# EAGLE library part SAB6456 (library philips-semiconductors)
Sensitive 1 GHz divide-by-64/divide-by-256 switchable prescaler Source: PHILIPS .. SAB6456.pdf
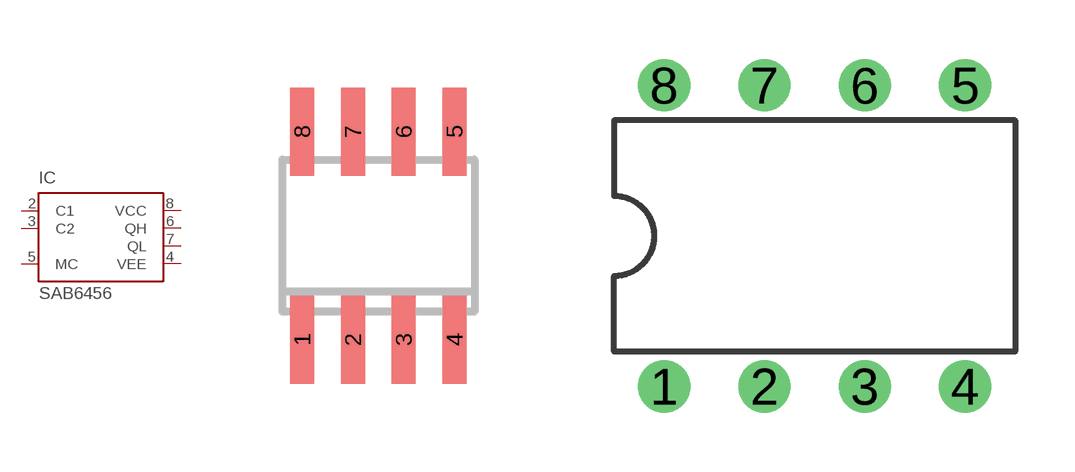
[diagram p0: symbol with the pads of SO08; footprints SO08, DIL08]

Designator prefix IC

## SAB6456T (OC_FARNELL: unknown; OC_NEWARK: unknown)  [SO08]
2  C1  in
3  C2  in
4  VEE  pwr
5  MC  in
6  QH  out
7  QL  out
8  VCC  pwr

## SAB6456 (OC_FARNELL: unknown; OC_NEWARK: unknown)  [DIL08]
Pads as for SO08

## Footprint SO08 (pad centres in mm)
Small Outline Package 8 NS Package M08A
smd 0.6 x 2.2: 1 -1.905,-2.6; 2 -0.635,-2.6; 3 0.635,-2.6; 4 1.905,-2.6; 5 1.905,2.6; 6 0.635,2.6; 7 -0.635,2.6; 8 -1.905,2.6

## Footprint DIL08 (pad centres in mm)
Dual In Line Package
drill 0.813 pad 1.27 round: 1 -3.81,-3.81; 2 -1.27,-3.81; 3 1.27,-3.81; 4 3.81,-3.81; 5 3.81,3.81; 6 1.27,3.81; 7 -1.27,3.81; 8 -3.81,3.81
